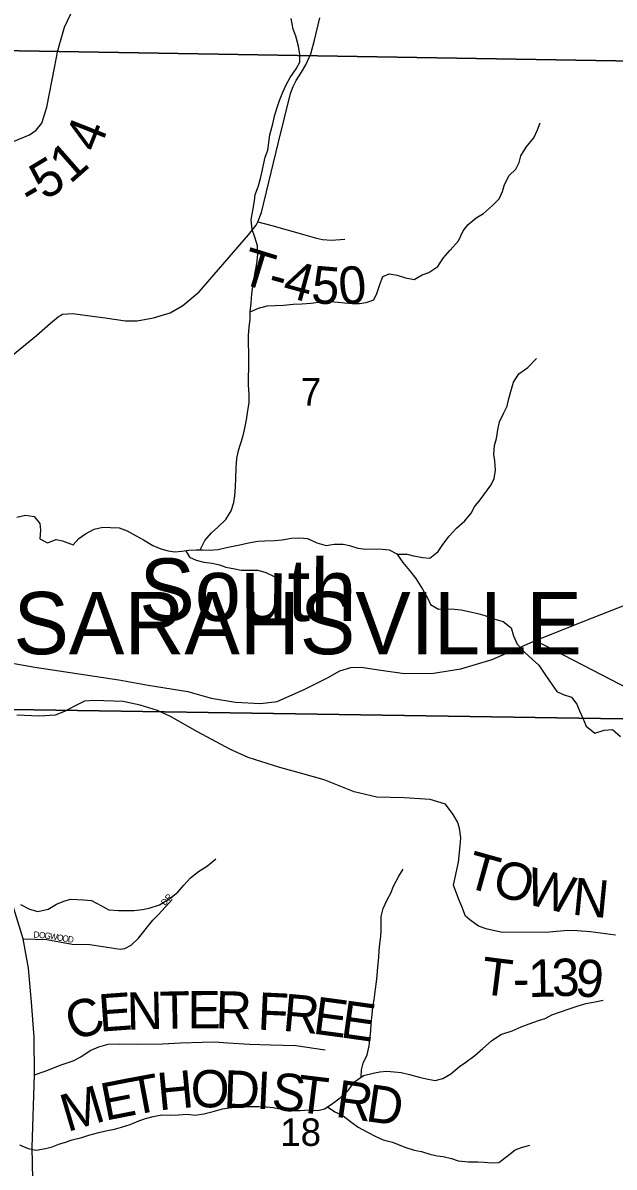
# Model space of a CAD drawing. Extents: x 2043100 to 2470832, y 443715 to 810583.
# Drawn here: x 2258956 to 2263711, y 656261 to 665453 of the extents above; entities that cross this region are included whole.
import ezdxf

# ---------------------------------------------------------------- set-up
doc = ezdxf.new("R2010")
doc.units = 0
for name, color, linetype in [('GM_X_Corporation_Text', 7, 'Continuous'), ('GM_X_Minor_River', 7, 'Continuous'), ('GM_X_Minor_River_Text', 7, 'Continuous'), ('GM_X_Section', 7, 'Continuous'), ('GM_X_Section_Text', 7, 'Continuous'), ('GM_X_State_Route', 7, 'Continuous'), ('GM_X_Township_Road', 7, 'Continuous'), ('GM_X_Township_Road_Text', 7, 'Continuous'), ('GM_X_Township_Subdivision', 7, 'Continuous'), ('GM_X_Township_Subdivision_Text', 7, 'Continuous')]:
    doc.layers.add(name, color=color, linetype=linetype)

msp = doc.modelspace()

# ---------------------------------------------------------------- linework, layer by layer
at = {"layer": 'GM_X_Minor_River'}
for points in [[(2260381.4, 661219.1), (2260418.6, 661293.6), (2260472, 661356.3), (2260523.5, 661400.9), (2260586.8, 661463.7), (2260630.1, 661532.2), (2260651.4, 661600.6), (2260660.8, 661652.8), (2260666.1, 661724.9), (2260669.3, 661795.1), (2260670.5, 661879.3), (2260677.7, 661953.5), (2260689, 662017.7), (2260723.9, 662126.2), (2260739.3, 662184.5), (2260754.4, 662264.8), (2260765.7, 662339.1), (2260775, 662399.3), (2260776.3, 662467.4), (2260771.5, 662545.5), (2260770.9, 662607.6), (2260772.1, 662679.7), (2260773.6, 662731.8), (2260772.8, 662808), (2260770.1, 662872), (2260769.4, 662940.2), (2260774.7, 663010.3), (2260784.1, 663068.5), (2260783.4, 663132.6), (2260790.7, 663200.8), (2260797.9, 663277), (2260805.3, 663333.2), (2260814.7, 663387.4), (2260822.2, 663437.6), (2260831.7, 663487.8), (2260841.1, 663541.9), (2260844.6, 663592.1), (2260841.9, 663662.2), (2260821.2, 663730.1), (2260800.6, 663792), (2260791.7, 663870), (2260805, 663944.3), (2260818.1, 664022.5), (2260823.6, 664074.7), (2260849, 664135), (2260866.3, 664201.3), (2260879.7, 664261.6), (2260891.1, 664311.8), (2260904.5, 664374), (2260925.9, 664430.3), (2260935.2, 664492.5), (2260942.6, 664552.7), (2260965.7, 664641.1), (2260982.9, 664713.4), (2261004.2, 664779.7), (2261019.7, 664829.9), (2261047, 664896.3), (2261072.4, 664954.7), (2261105.8, 665013.1), (2261153, 665083.7), (2261182.5, 665138.1), (2261183.8, 665198.2), (2261173.1, 665266.2), (2261150.3, 665346.1), (2261129.8, 665402), (2261112.9, 665487.9)], [(2260783.4, 663130.6), (2260851.1, 663161.4), (2260920.9, 663180.1), (2260984.8, 663182.8), (2261050.8, 663185.5), (2261130.7, 663192.3), (2261200.6, 663195), (2261272.5, 663201.8), (2261354.4, 663210.6), (2261426.4, 663213.3), (2261492.4, 663208), (2261542.4, 663202.5), (2261604.5, 663199.1), (2261662.4, 663199.7), (2261716.3, 663206.3), (2261778.1, 663228.9), (2261803.6, 663279.3), (2261826.8, 663351.7), (2261850.1, 663414), (2261901.9, 663436.6), (2261966, 663425.2), (2262034.2, 663403.8), (2262102.3, 663392.5), (2262167.9, 663429.2), (2262219.7, 663447.8), (2262293.2, 663494.6), (2262336.5, 663563.2), (2262391.8, 663625.9), (2262459, 663700.7), (2262496.1, 663781.2), (2262537.6, 663833.7), (2262601, 663886.4), (2262660.6, 663921.1), (2262733.9, 663986), (2262787.4, 664038.6), (2262812.8, 664096.9), (2262828.2, 664155.2), (2262867.4, 664225.7), (2262920.9, 664278.4), (2262948.3, 664330.7), (2262959.7, 664384.9), (2263003, 664455.5), (2263064.2, 664528.2), (2263093.5, 664592.6), (2263117, 664649)], [(2261965.3, 661184.3), (2262047.3, 661184.1), (2262097.4, 661170.6), (2262173.5, 661157.3), (2262227.5, 661153.9), (2262296.9, 661206.7), (2262334.4, 661261.2), (2262385.6, 661329.8), (2262442.9, 661394.5), (2262510.3, 661453.3), (2262561.7, 661513.9), (2262589.1, 661564.3), (2262634.5, 661620.8), (2262721.2, 661741.9), (2262746.7, 661792.3), (2262758, 661858.5), (2262751.2, 661934.6), (2262744.7, 661986.6), (2262749.9, 662058.8), (2262765.4, 662113), (2262774.6, 662183.3), (2262788, 662247.5), (2262823.2, 662320), (2262850.7, 662372.4), (2262862.1, 662424.6), (2262879.4, 662490.9), (2262902.6, 662565.2), (2262943.9, 662633.8), (2263017.4, 662684.6), (2263086.6, 662757.4)], [(2258907.2, 661482.6), (2258977, 661497.3), (2259047.1, 661486), (2259091.6, 661432.3), (2259096.2, 661378.3), (2259090.9, 661308.1), (2259153.3, 661274.7), (2259222.9, 661303.5), (2259275, 661292), (2259361.3, 661260.8), (2259404.8, 661311.3), (2259458.4, 661347.9), (2259528, 661386.7), (2259597.8, 661401.5), (2259659.8, 661398.1), (2259729.8, 661396.8), (2259794, 661373.4), (2259866.4, 661332.1), (2259926.7, 661300.6), (2260001.2, 661255.3), (2260065.5, 661227.9), (2260123.6, 661210.5), (2260177.7, 661203), (2260233.6, 661207.6), (2260291.5, 661216.2), (2260349.4, 661218.8), (2260403.4, 661219.3), (2260457.4, 661217.9), (2260525.4, 661222.6), (2260593.2, 661239.3), (2260700.9, 661260.4), (2260770.7, 661275.2), (2260846.5, 661290), (2260902.5, 661292.6), (2260978.4, 661295.3), (2261042.4, 661300), (2261116.2, 661312.8), (2261180.2, 661315.4), (2261246.2, 661310.1), (2261320.5, 661274.8), (2261394.7, 661253.5), (2261458.6, 661264.2), (2261532.6, 661264.9), (2261582.7, 661253.4), (2261648.9, 661232.1), (2261714.9, 661224.7), (2261776.9, 661227.4), (2261848.9, 661224.1), (2261900.9, 661220.6), (2261963.2, 661187.2), (2262011.9, 661117.6), (2262064.6, 661054), (2262115.3, 660988.4), (2262170.1, 660904.8)], [(2260265.8, 661212.4), (2260296.1, 661160.2), (2260348.3, 661136.6), (2260412.4, 661121.3), (2260478.5, 661111.9), (2260536.6, 661098.5), (2260588.8, 661081), (2260660.9, 661065.7), (2260711, 661056.2), (2260781, 661056.9), (2260845, 661055.6), (2260909.1, 661038.2), (2260977.5, 661004.8)], [(2262170.1, 660904.8), (2262208.8, 660835.1), (2262235.4, 660779.3), (2262299.7, 660743.9), (2262369.7, 660744.6), (2262427.7, 660743.2), (2262481.8, 660737.7), (2262541.9, 660724.3), (2262616, 660707), (2262670.2, 660691.6), (2262742.4, 660666.3), (2262818.6, 660643), (2262883.1, 660593.6), (2262901.8, 660529.7), (2262930.5, 660461.8), (2262991.1, 660398.3), (2263053.7, 660338.9), (2263106.2, 660293.3), (2263154.9, 660219.7), (2263213.7, 660136.2), (2263250.3, 660080.4), (2263300.5, 660056.9), (2263368.7, 660035.6), (2263411.3, 659979.9), (2263433.9, 659926.1), (2263458.4, 659868.2), (2263485.1, 659802.4), (2263555.7, 659747), (2263631.4, 659771.8), (2263699.3, 659776.5), (2263761.9, 659721.1)], [(2258935.5, 658371.3), (2259007.9, 658332), (2259076.1, 658314.7), (2259159.8, 658333.5), (2259227.4, 658372.3), (2259285.1, 658396.9), (2259339, 658413.5), (2259443, 658406.6), (2259507, 658401.2), (2259587.4, 658360), (2259645.7, 658326.5), (2259723.8, 658321.3), (2259851.7, 658322.6), (2259917.6, 658329.3), (2259971.5, 658339.9), (2260053.2, 658366.8), (2260136.6, 658417.7), (2260202.1, 658470.5), (2260251.5, 658525), (2260304.8, 658583.7), (2260368.3, 658634.4), (2260439.8, 658681.2), (2260507.2, 658736)], [(2261675.5, 656983.7), (2261678.3, 657043.3), (2261691.8, 657095.5), (2261725.1, 657162), (2261740.3, 657234.2), (2261745.8, 657288.4), (2261753, 657356.5), (2261756.5, 657410.7), (2261763.7, 657486.9), (2261771.1, 657549), (2261780.5, 657603.2), (2261791.6, 657689.5), (2261799, 657749.7), (2261806.4, 657799.8), (2261811.7, 657870), (2261818.9, 657944.2), (2261822.4, 657998.3), (2261827.8, 658054.4), (2261835.2, 658112.6), (2261836.7, 658164.7), (2261836.1, 658220.8), (2261837.5, 658274.9), (2261852.8, 658339.2), (2261886.1, 658407.6), (2261915.5, 658462), (2261937, 658518.3), (2261980.1, 658596.9), (2262013.5, 658653.3)], [(2258929.5, 656440.2), (2258997.8, 656410.8), (2259061.9, 656397.5), (2259137.8, 656410.3), (2259191.6, 656422.8), (2259245.4, 656445.4), (2259297.2, 656460), (2259351, 656478.5), (2259428.7, 656499.4), (2259486.5, 656518), (2259566.3, 656538.8), (2259624.1, 656551.5), (2259692, 656566.2), (2259749.8, 656582.8), (2259817.5, 656603.5), (2259889.2, 656632.3), (2259943, 656650.9), (2260002.8, 656667.5), (2260072.6, 656680.2), (2260144.6, 656679), (2260208.6, 656679.6), (2260280.5, 656686.4), (2260338.6, 656679), (2260410.4, 656689.7), (2260486.2, 656706.5), (2260562, 656729.3), (2260615.9, 656735.9), (2260675.8, 656744.5), (2260735.7, 656747.2), (2260801.7, 656747.8), (2260853.7, 656746.4), (2260913.7, 656745), (2260969.7, 656739.5), (2261025.8, 656730.1), (2261075.8, 656724.6), (2261127.9, 656715.1), (2261185.9, 656715.7), (2261259.8, 656720.5), (2261327.8, 656715.2), (2261381.7, 656729.8), (2261435.3, 656762.4), (2261508.7, 656817.2), (2261572.1, 656875.9), (2261623.3, 656946.6), (2261694.8, 656997.4), (2261772.6, 657016.2), (2261826.4, 657026.8), (2261882.4, 657031.4), (2261942.4, 657026), (2261998.4, 657020.5), (2262066.6, 657005.2), (2262142.8, 656982), (2262200.9, 656970.5), (2262271, 656957.2), (2262332.8, 656971.9), (2262396.4, 657010.6), (2262467.8, 657069.4), (2262519.4, 657104), (2262590.8, 657156.8), (2262656.2, 657213.6), (2262725.5, 657276.4), (2262799, 657325.2), (2262890.7, 657356.2), (2262962.3, 657387), (2263028, 657411.7), (2263103.7, 657438.6), (2263155.5, 657455.1), (2263211.2, 657483.7), (2263281, 657508.5), (2263348.7, 657531.2), (2263414.4, 657553.9), (2263484.2, 657574.7), (2263558, 657587.5), (2263621.9, 657602.1)], [(2261406.9, 656745.1), (2261465.9, 656704.6), (2261522.1, 656681.1), (2261600.7, 656619.8), (2261653.1, 656580.3), (2261727.5, 656541), (2261793.8, 656505.7), (2261854.1, 656480.2), (2261928.3, 656461), (2262026.6, 656421.9), (2262102.8, 656396.7), (2262160.9, 656385.2), (2262229.1, 656363.9), (2262287.3, 656350.5), (2262337.3, 656345), (2262403.4, 656329.6), (2262455.6, 656310.2), (2262539.7, 656303), (2262615.6, 656301.8), (2262665.6, 656300.3), (2262723.7, 656294.9), (2262783.6, 656297.5), (2262851.1, 656348.3), (2262914.5, 656399), (2262966.3, 656417.6), (2263034.1, 656436.3)]]:
    msp.add_lwpolyline(points, dxfattribs=at)
at = {"layer": 'GM_X_Section'}
for points in [[(2264124.5, 670417.5), (2264044.6, 665142.3), (2258605.2, 665232.3), (2258713.1, 670509.8)], [(2264044.6, 665142.3), (2263952.7, 659859), (2258515.4, 659943), (2258605.2, 665232.3)], [(2263952.7, 659859), (2263921.3, 654536.4), (2258418.4, 654585.6), (2258515.4, 659943)]]:
    msp.add_lwpolyline(points, close=True, dxfattribs=at)
at = {"layer": 'GM_X_State_Route'}
for points in [[(2258813.3, 662734.7), (2259066.2, 662941), (2259177.6, 663040), (2259239.3, 663090.6), (2259273.2, 663112.9), (2259355.3, 663117.5), (2259618, 663083.2), (2259782.4, 663060.3), (2259874.5, 663059), (2260006.5, 663082), (2260140.4, 663123), (2260242.2, 663181.9), (2260373.5, 663291.1), (2260770.8, 663749), (2260832.3, 663827.7), (2260845.7, 663855), (2260875.6, 663930.2), (2261011.7, 664494.6), (2261106.9, 664886.2), (2261128.5, 664942.5), (2261154.2, 664990.8), (2261197.8, 665057.2), (2261231.4, 665115.6), (2261272.8, 665204.1), (2261300.1, 665314.6), (2261342.8, 665493.3)], [(2263078.1, 660491.1), (2263462, 660644), (2263912.5, 660821.6), (2264199, 660966.5), (2264421.9, 661171.5), (2264430.3, 661179.3)], [(2260282.9, 660080.2), (2260470, 660027.6), (2260666.9, 659994.6), (2260867.6, 659985.7), (2261001.7, 660001.8), (2261222.7, 660099.5), (2261405.8, 660190.7), (2261505.2, 660248.4), (2261593, 660273.8), (2261677.2, 660277.1), (2261835.9, 660253.5), (2262024.8, 660226.4), (2262257.3, 660228), (2262477.4, 660263.5), (2262730.9, 660337.7), (2263078.1, 660491.1), (2265870.2, 659048.4)], [(2258494.3, 660376.2), (2259050.7, 660276.4), (2259726.7, 660175.7), (2259963.1, 660132.1), (2260282.9, 660080.2)], [(2259044.2, 655784.1), (2259029.1, 656418.1), (2259049.9, 657001.4), (2259047.7, 657305.1), (2259025.8, 657584.5), (2259001.2, 657860), (2258957.5, 658094.1), (2258872, 658372.7), (2258786.1, 658556.8), (2258658.6, 658712.5), (2258544.1, 658805.5), (2258484.5, 658853.2), (2258448.7, 658896.1), (2258412.7, 658952), (2258410.1, 659028.2), (2258413.6, 659187.1), (2258421.9, 659309.7), (2258423.3, 659329.1)]]:
    msp.add_lwpolyline(points, dxfattribs=at)
at = {"layer": 'GM_X_Township_Road'}
for points in [[(2258554, 664280.9), (2258554.8, 664281.8), (2258585.3, 664317.1), (2258676.9, 664393.9), (2258780.6, 664458.8), (2259008.2, 664554.6), (2259062, 664591.1), (2259107.7, 664647.6), (2259148.8, 664776.2), (2259210.6, 665091.4), (2259237.6, 665231.9), (2259259.1, 665306.2), (2259290.3, 665418.7), (2259457.9, 665772.7)], [(2260845.7, 663855), (2260958.5, 663824.5), (2261203.4, 663754.1), (2261317.8, 663722.8), (2261365.9, 663713.1), (2261438.1, 663707.6), (2261546.2, 663714.4)], [(2263720.9, 658124.6), (2263522.1, 658151.9), (2263414.9, 658159.6), (2263338.9, 658161.6), (2263188.8, 658148), (2262814.5, 658146), (2262689.7, 658171.3), (2262619.6, 658196.7), (2262549.4, 658247.4), (2262515.6, 658277.8), (2262485.1, 658354.6), (2262461.7, 658411.1), (2262418.8, 658526.1), (2262458.4, 658710.3), (2262473.4, 658842.7), (2262477, 658904.9), (2262466.4, 658983), (2262452, 659035), (2262415.5, 659092.9), (2262354.5, 659175.2), (2262231.7, 659214.2), (2262021.1, 659227.9), (2261802.8, 659233.7), (2261619.6, 659276.6), (2261379.8, 659372.1), (2261206.3, 659418.9), (2261023.1, 659471.5), (2260767.7, 659551.4), (2260625.4, 659615.8), (2260360.3, 659758.1), (2260142, 659880.9), (2260038.7, 659929.6), (2259898.3, 659971.5), (2259761.9, 660001.7), (2259529, 660009.5), (2259451, 660002.7), (2259372, 659963.7), (2259290.2, 659919.9), (2259214.1, 659892.6), (2259089.4, 659882.8), (2258907.1, 659892.6)], [(2259049.9, 657001.4), (2259134.3, 657031.2), (2259264.3, 657081.3), (2259359.7, 657113.4), (2259422.9, 657145.6), (2259498, 657196.9), (2259567.2, 657226.7), (2259641.1, 657247), (2259729.4, 657250.6), (2259879.6, 657248.2), (2260077.5, 657250.6), (2260223, 657260.1), (2260397.1, 657263.7), (2260496.1, 657266.1), (2260603.4, 657260.1), (2260777.5, 657249.4), (2260948, 657242.2), (2261150.7, 657236.3), (2261386.8, 657202.9)]]:
    msp.add_lwpolyline(points, dxfattribs=at)
at = {"layer": 'GM_X_Township_Subdivision'}
msp.add_lwpolyline([(2258957.5, 658094.1), (2259147.4, 658088.2), (2259352.1, 658051.1), (2259494.1, 658049.6), (2259738, 658010.7), (2259774.8, 658015.7), (2259826, 658043.7), (2259886.8, 658098.8), (2260000, 658245.1), (2260047.5, 658289.4), (2260155.4, 658409.6)], dxfattribs=at)

# ---------------------------------------------------------------- texts
at = {"layer": 'GM_X_Corporation_Text'}
msp.add_text('SARAHSVILLE', height=500, rotation=0.00001, dxfattribs=at).set_placement((2258879.9, 660381.1))
at = {"layer": 'GM_X_Minor_River_Text'}
msp.add_text('South', height=499.99, rotation=359.85086, dxfattribs=at).set_placement((2259891.7, 660651))
at = {"layer": 'GM_X_Section_Text'}
for s, height, p in [('7', 220.8, (2261190.6, 662378.2)), ('18', 220.83, (2261025.6, 656431))]:
    msp.add_text(s, height=height, rotation=0.00001, dxfattribs=at).set_placement(p)
at = {"layer": 'GM_X_Township_Road_Text'}
for s, rotation, p in [('4', 68.45689, (2259562.7, 664400.5)), ('1', 41.32871, (2259335.7, 664152.9)), ('5', 31.08935, (2259130.3, 664023)), ('-', 30.77058, (2259022.9, 663959)), ('T', 342.87427, (2260688.9, 663366.2)), ('4', 344.82273, (2261032.7, 663263.8)), ('5', 355.06433, (2261268.5, 663205.2)), ('0', 4.39167, (2261505.8, 663189)), ('-', 344.35859, (2260911.5, 663297.7)), ('T', 344.40134, (2262501.7, 658514.8)), ('O', 344.40123, (2262717.9, 658454.4)), ('W', 346.07194, (2262981.4, 658381)), ('N', 354.45066, (2263365.9, 658289.3)), ('T', 352.8197, (2262628.5, 657654.3)), ('1', 1.08249, (2263022.7, 657626.8)), ('3', 2.51493, (2263215.6, 657630.6)), ('9', 353.87877, (2263388.3, 657639)), ('-', 1.39817, (2262900, 657623.8)), ('C', 19.75936, (2259363.5, 657269)), ('E', 4.19065, (2259574.4, 657347.9)), ('N', 1.27505, (2259794.2, 657364.1)), ('T', 1.18296, (2260058, 657369.9)), ('E', 0.27857, (2260281.1, 657374.6)), ('R', 358.50109, (2260503, 657375.7)), ('F', 357.35256, (2260840.1, 657365.6)), ('R', 354.77836, (2261038.7, 657356.5)), ('E', 352.33173, (2261280.7, 657334.4)), ('E', 351.97657, (2261502.6, 657304.6)), ('E', 11.05274, (2259617.4, 656632.7)), ('T', 10.64256, (2259837.1, 656675.6)), ('H', 5.4652, (2260050.5, 656716)), ('O', 359.83608, (2260305.5, 656740.8)), ('D', 357.7883, (2260566.7, 656740.1)), ('I', 357.25141, (2260829.8, 656730)), ('S', 354.65157, (2260949.2, 656724.3)), ('T', 353.05306, (2261148.6, 656705.7)), ('M', 16.55072, (2259312.7, 656541.7)), ('R', 351.9527, (2261461.3, 656666.2)), ('D', 351.76481, (2261705.1, 656631.8))]:
    msp.add_text(s, height=300, rotation=rotation, dxfattribs=at).set_placement(p)
at = {"layer": 'GM_X_Township_Subdivision_Text'}
for s, rotation, p in [('DR', 47.28921, (2260097.4, 658357.8)), ('D', 355.07664, (2259039.6, 658105.5)), ('O', 355.08213, (2259083.5, 658101.7)), ('G', 353.16504, (2259126.9, 658098)), ('W', 350.60955, (2259170, 658092.8)), ('O', 350.33644, (2259226.3, 658083.5)), ('O', 350.33644, (2259269.7, 658076.1)), ('D', 351.94222, (2259314.6, 658068.5))]:
    msp.add_text(s, height=50, rotation=rotation, dxfattribs=at).set_placement(p)

doc.saveas('drawing.dxf')
